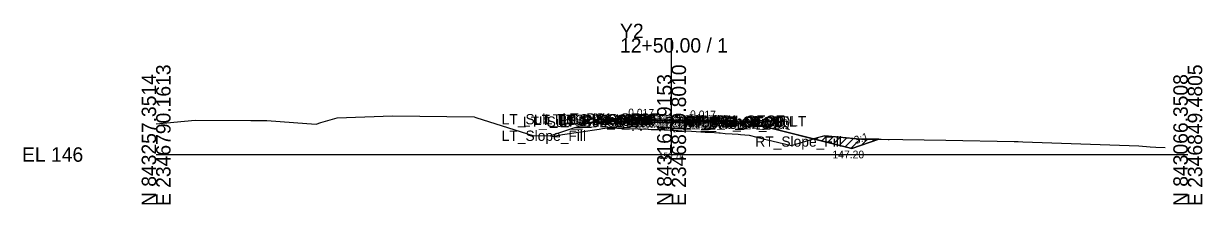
# Model space of a CAD drawing. Extents: x -26 to 2346977, y -10 to 843253.
# Drawn here: x -25.7 to 202.8, y 1990.3 to 2025.4 of the extents above; entities that cross this region are included whole.
import ezdxf

# ---------------------------------------------------------------- set-up
doc = ezdxf.new("R2010")
doc.units = 0
for name, color, linetype in [('Default', 7, 'Continuous'), ('Exist Cross Section Cell', 7, 'Continuous'), ('Exist XS Center Line Elevation Label', 7, 'Continuous'), ('Exist XS Ground Line', 7, 'Continuous'), ('Prop CMT Pvmt Course 1', 7, 'Continuous'), ('Prop CMT Pvmt Course 2', 7, 'Continuous'), ('Prop CMT Pvmt Course 3', 7, 'Continuous'), ('Prop CMT Pvmt Surface', 7, 'Continuous'), ('Prop CMT Pvmt Surface Shoulder', 7, 'Continuous'), ('Prop CMT Shld Paved Course 1', 7, 'Continuous'), ('Prop CMT Shld Paved Course 2', 7, 'Continuous'), ('Prop CMT Shld Paved Course 3', 7, 'Continuous'), ('Prop CMT Slope Grass', 7, 'Continuous'), ('Prop CMT Subgrade Earthwork', 7, 'Continuous'), ('Prop Road Sect_ Recs - UUC (Outline)', 7, 'Continuous'), ('Prop Road Sect_ Recs - UUC (pattern)', 7, 'Continuous'), ('Prop XS Earthwork Shape', 7, 'Continuous'), ('Prop XS SE Text', 7, 'Continuous'), ('Prop XS Side Slope Text', 7, 'Continuous'), ('Scratch_Level_2', 7, 'Continuous')]:
    doc.layers.add(name, color=color, linetype=linetype)

msp = doc.modelspace()

# ---------------------------------------------------------------- linework, layer by layer
at = {"layer": 'Exist Cross Section Cell'}
for p, q in [((99.93, 2000), (99.93, 2022.59)), ((0, 2000), (99.93, 2000)), ((99.93, 2000), (200, 2000))]:
    msp.add_line(p, q, dxfattribs=at)
at = {"layer": 'Exist XS Ground Line'}
msp.add_lwpolyline([(0, 2005.99), (7.59, 2006.64), (18.36, 2006.62), (21.44, 2006.61), (29.23, 2006.04), (31.01, 2005.92), (31.92, 2006.2), (35.07, 2007.11), (45.82, 2007.53), (61.63, 2007.29), (62.01, 2007.17), (73.2, 2003.61), (73.68, 2003.71), (76.58, 2003.65), (76.74, 2003.52), (78.79, 2003.86), (85.91, 2004.94), (86.54, 2005.04), (87.46, 2005.18), (88.16, 2005.17), (89.42, 2005.13), (90.77, 2005.08), (93.48, 2004.98), (95.41, 2004.91), (96, 2004.89), (97.41, 2004.83), (98.62, 2004.79), (100.02, 2004.73), (100.72, 2004.69), (101.19, 2004.66), (101.94, 2004.62), (103.82, 2004.52), (104.69, 2004.46), (106.44, 2004.36), (107.35, 2004.31), (109.08, 2004.2), (109.38, 2004.18), (110.35, 2004.11), (111.66, 2004.02), (112.82, 2003.93), (113.29, 2003.89), (114.97, 2003.73), (117.94, 2002.99), (118.53, 2002.84), (119.35, 2002.64), (123.16, 2001.78), (128.92, 2003.48), (129.66, 2003.65), (136.76, 2002.97), (140.55, 2002.96), (153.1, 2002.76), (166.33, 2002.54), (167.14, 2002.52), (168, 2002.46), (190.49, 2001.69), (192.73, 2001.49), (193.83, 2001.43), (195.59, 2001.34)], dxfattribs=at)
at = {"layer": 'Prop CMT Pvmt Course 1'}
for p, q in [((99.93, 2006.78), (88, 2006.99)), ((88, 2006.99), (88, 2006.74)), ((88, 2006.74), (99.93, 2006.53)), ((99.93, 2006.53), (99.93, 2006.78)), ((99.93, 2006.78), (112, 2006.58)), ((99.93, 2006.53), (99.93, 2006.78)), ((99.93, 2006.53), (99.93, 2006.66)), ((99.93, 2006.66), (99.93, 2006.66)), ((99.93, 2006.66), (99.93, 2006.53)), ((99.93, 2006.53), (99.93, 2006.66)), ((99.93, 2006.66), (99.93, 2006.66)), ((99.93, 2006.66), (99.93, 2006.53)), ((99.93, 2006.53), (99.93, 2006.53)), ((112, 2006.33), (99.93, 2006.53)), ((99.93, 2006.53), (99.93, 2006.53)), ((112, 2006.58), (112, 2006.33))]:
    msp.add_line(p, q, dxfattribs=at)
at = {"layer": 'Prop CMT Pvmt Course 2'}
for p, q in [((88, 2006.74), (99.93, 2006.53)), ((99.93, 2006.53), (88, 2006.74)), ((88, 2006.74), (88, 2006.74)), ((99.93, 2006.53), (99.93, 2006.53)), ((112, 2006.33), (99.93, 2006.53)), ((99.93, 2006.53), (99.93, 2006.53)), ((99.93, 2006.53), (112, 2006.33)), ((112, 2006.33), (112, 2006.33))]:
    msp.add_line(p, q, dxfattribs=at)
at = {"layer": 'Prop CMT Pvmt Course 3'}
for p, q in [((99.93, 2006.53), (88, 2006.74)), ((88, 2006.74), (88, 2006.4)), ((99.93, 2006.2), (99.93, 2006.53)), ((99.93, 2006.53), (112, 2006.33)), ((99.93, 2006.2), (99.93, 2006.53)), ((88, 2006.4), (99.93, 2006.2)), ((112, 2006), (99.93, 2006.2)), ((112, 2006.33), (112, 2006))]:
    msp.add_line(p, q, dxfattribs=at)
at = {"layer": 'Prop CMT Pvmt Surface'}
for q in [(88, 2006.99), (112, 2006.58)]:
    msp.add_line((99.93, 2006.78), q, dxfattribs=at)
at = {"layer": 'Prop CMT Pvmt Surface Shoulder'}
for p, q in [((88, 2006.99), (88, 2006.99)), ((112, 2006.58), (112, 2006.58))]:
    msp.add_line(p, q, dxfattribs=at)
at = {"layer": 'Prop CMT Shld Paved Course 1'}
for p, q in [((88, 2006.99), (87.74, 2006.73)), ((87.74, 2006.73), (88, 2006.74)), ((88, 2006.99), (88, 2006.99)), ((88, 2006.74), (88, 2006.99)), ((112, 2006.58), (112, 2006.58)), ((112, 2006.58), (112.25, 2006.32)), ((112, 2006.33), (112, 2006.58)), ((112.25, 2006.32), (112, 2006.33))]:
    msp.add_line(p, q, dxfattribs=at)
at = {"layer": 'Prop CMT Shld Paved Course 2'}
for p, q in [((88, 2006.74), (87.74, 2006.73)), ((87.74, 2006.73), (88, 2006.74)), ((87.74, 2006.73), (87.74, 2006.73)), ((88, 2006.74), (88, 2006.74)), ((112, 2006.33), (112.25, 2006.32)), ((112.25, 2006.32), (112, 2006.33)), ((112, 2006.33), (112, 2006.33)), ((112.25, 2006.32), (112.25, 2006.32))]:
    msp.add_line(p, q, dxfattribs=at)
at = {"layer": 'Prop CMT Shld Paved Course 3'}
for p, q in [((87.24, 2006.72), (86.9, 2006.38)), ((87.74, 2006.73), (87.24, 2006.72)), ((88, 2006.74), (87.74, 2006.73)), ((88, 2006.4), (88, 2006.74)), ((86.9, 2006.38), (88, 2006.4)), ((112, 2006.33), (112.25, 2006.32)), ((112, 2006), (112, 2006.33)), ((113.1, 2005.97), (112, 2006)), ((112.25, 2006.32), (112.75, 2006.31)), ((112.75, 2006.31), (113.1, 2005.97))]:
    msp.add_line(p, q, dxfattribs=at)
at = {"layer": 'Prop CMT Slope Grass'}
for p, q in [((86, 2006.83), (76.47, 2003.65)), ((88, 2006.99), (86, 2006.83)), ((112, 2006.58), (114, 2006.42)), ((114, 2006.42), (134.87, 2001.2)), ((134.87, 2001.2), (140.14, 2002.96))]:
    msp.add_line(p, q, dxfattribs=at)
at = {"layer": 'Prop CMT Subgrade Earthwork'}
for p, q in [((86.9, 2006.38), (86.43, 2006.86)), ((88, 2006.4), (86.9, 2006.38)), ((99.93, 2006.2), (88, 2006.4)), ((99.93, 2006.2), (112, 2006)), ((112, 2006), (113.1, 2005.97)), ((113.1, 2005.97), (113.57, 2006.45))]:
    msp.add_line(p, q, dxfattribs=at)
at = {"layer": 'Prop Road Sect_ Recs - UUC (Outline)'}
msp.add_lwpolyline([(127.47, 2003.05), (134.87, 2001.2), (134.87, 2001.2), (134.87, 2001.2), (140.13, 2002.95), (136.5, 2002.99), (129.66, 2003.65)], close=True, dxfattribs=at)
msp.add_lwpolyline([(127.47, 2003.05), (134.87, 2001.2), (134.87, 2001.2), (134.87, 2001.2), (140.13, 2002.95), (136.5, 2002.99), (129.66, 2003.65)], close=True, dxfattribs=at)
at = {"layer": 'Prop Road Sect_ Recs - UUC (pattern)'}
for p, q in [((127.95, 2002.93), (128.29, 2003.27)), ((127.95, 2002.93), (128.29, 2003.27)), ((129.08, 2002.65), (130.04, 2003.61)), ((129.08, 2002.65), (130.04, 2003.61)), ((130.21, 2002.37), (131.33, 2003.49)), ((130.21, 2002.37), (131.33, 2003.49)), ((131.34, 2002.08), (132.62, 2003.36)), ((131.34, 2002.08), (132.62, 2003.36)), ((132.47, 2001.8), (133.91, 2003.24)), ((132.47, 2001.8), (133.91, 2003.24)), ((133.61, 2001.52), (135.2, 2003.12)), ((133.61, 2001.52), (135.2, 2003.12)), ((134.74, 2001.23), (136.5, 2002.99)), ((134.74, 2001.23), (136.5, 2002.99)), ((136.77, 2001.84), (137.89, 2002.98)), ((136.77, 2001.84), (137.89, 2002.98)), ((138.86, 2002.53), (139.29, 2002.96)), ((138.86, 2002.53), (139.29, 2002.96)), ((141.97, 2002.81), (142.09, 2002.93)), ((141.97, 2002.81), (142.09, 2002.93))]:
    msp.add_line(p, q, dxfattribs=at)
at = {"layer": 'Prop XS Earthwork Shape'}
for points in [[(86.9, 2006.38), (86.43, 2006.86), (86, 2006.83), (76.47, 2003.65), (76.58, 2003.65), (76.74, 2003.52), (78.79, 2003.86), (85.91, 2004.94), (86.54, 2005.04), (87.46, 2005.18), (88.16, 2005.17), (89.42, 2005.13), (90.77, 2005.08), (93.48, 2004.98), (95.41, 2004.91), (96, 2004.89), (97.41, 2004.83), (98.62, 2004.79), (100.02, 2004.73), (100.72, 2004.69), (101.19, 2004.66), (101.94, 2004.62), (103.82, 2004.52), (104.69, 2004.46), (106.44, 2004.36), (107.35, 2004.31), (109.08, 2004.2), (109.38, 2004.18), (110.35, 2004.11), (111.66, 2004.02), (112.82, 2003.93), (113.29, 2003.89), (114.97, 2003.73), (117.94, 2002.99), (118.53, 2002.84), (119.35, 2002.64), (123.16, 2001.78), (127.47, 2003.05), (114, 2006.42), (113.57, 2006.45), (113.1, 2005.97), (112, 2006), (99.93, 2006.2), (88, 2006.4)], [(129.66, 2003.65), (136.76, 2002.97), (140.14, 2002.96), (134.87, 2001.2), (127.47, 2003.05), (128.92, 2003.48)]]:
    msp.add_lwpolyline(points, close=True, dxfattribs=at)

# ---------------------------------------------------------------- texts
at = {"layer": 'Default'}
for s, height, p in [('-', 0.0001, (0, 2000)), ('147.20', 1.5, (131.12, 1999.26))]:
    msp.add_text(s, height=height, dxfattribs=at).set_placement(p)
at = {"layer": 'Exist Cross Section Cell'}
for s, p in [('Y2', (89.93, 2022.59)), ('12+50.00 / 1', (89.93, 2019.79)), ('EL 146', (-26, 1998.6))]:
    msp.add_text(s, height=2.8, dxfattribs=at).set_placement(p)
for s, p in [('E 2346790.1613', (2.8, 1990)), ('E 2346819.8010', (102.73, 1990)), ('E 2346849.4805', (202.8, 1990)), ('N 843257.3514', (0, 1990)), ('N 843161.9153', (99.93, 1990)), ('N 843066.3508', (200, 1990))]:
    msp.add_text(s, height=2.8, rotation=90, dxfattribs=at).set_placement(p)
at = {"layer": 'Exist XS Center Line Elevation Label'}
msp.add_text('150.74', height=1.2, dxfattribs=at).set_placement((97.44, 1999.14))
at = {"layer": 'Prop XS SE Text'}
for s, rotation, p in [('0.017', 359.0299, (91.5, 2007.41)), ('0.017', 359.0299, (103.5, 2007.08)), ('4:1', 345.9638, (120.18, 2005.41)), ('3:1', 18.4349, (135.6, 2002.01))]:
    msp.add_text(s, height=1.5, rotation=rotation, dxfattribs=at).set_placement(p)
at = {"layer": 'Prop XS Side Slope Text'}
msp.add_text('3:1', height=1.5, rotation=18.4332, dxfattribs=at).set_placement((81.26, 2005.47))
at = {"layer": 'Scratch_Level_2'}
for s, p in [('LT_Sub_Trench_Out_DLT', (66.99, 2005.86)), ('LT_Sub_Trench_Out', (71.11, 2005.38)), ('LT_PS3_Shelf_Out', (73.23, 2005.72)), ('LT_GS_OS_CTL', (75.37, 2005.83)), ('LT_PS3_OEOP', (77.98, 2005.73)), ('LT_PS2_OEOP', (77.98, 2005.73)), ('LT_Sub_OEOT', (78.08, 2005.4)), ('LT_PV3_OEOT', (78.17, 2005.74)), ('LT_PV2_OEOT', (78.17, 2005.74)), ('LT_PV1_OEOT', (78.74, 2005.99)), ('LT_PS1_OEOP', (78.8, 2005.99)), ('RT_Sub_OEEOP', (89.1, 2005.2)), ('LT_Sub_OEEOP', (89.15, 2005.2)), ('RT_PV2_OEEOP', (89.19, 2005.53)), ('RT_PV3_OEEOP', (89.19, 2005.53)), ('LT_PV2_OEEOP', (89.24, 2005.53)), ('LT_PV3_OEEOP', (89.24, 2005.53)), ('RT_PV1_OEEOP', (89.76, 2005.66)), ('LT_PV1_OEEOP', (89.81, 2005.66)), ('RT_PV2_IEEOP', (89.84, 2005.53)), ('LT_PV2_IEEOP', (89.89, 2005.53)), ('RT_PV1_IEEOP', (90.41, 2005.66)), ('LT_PV1_IEEOP', (90.45, 2005.66)), ('PV2_PGL', (93.84, 2005.53)), ('RT_Sub_Trench_Out_DLT', (94.09, 2005.45)), ('PV1_PGL', (94.41, 2005.78)), ('RT_Sub_Trench_Out', (97.25, 2004.97)), ('RT_PS3_Shelf_Out', (98.69, 2005.31)), ('RT_Sub_OEOT', (102.03, 2005)), ('RT_PV3_OEOT', (102.13, 2005.33)), ('RT_PV2_OEOT', (102.13, 2005.33)), ('RT_PS3_OEOP', (102.44, 2005.32)), ('RT_PS2_OEOP', (102.44, 2005.32)), ('RT_PV1_OEOT', (102.69, 2005.58)), ('RT_PS1_OEOP', (102.76, 2005.58)), ('RT_GS_OS_CTL', (103.32, 2005.42)), ('LT_Slope_Fill', (66.99, 2002.65)), ('RT_Slope_Fill', (116.16, 2001.52))]:
    msp.add_text(s, height=2, dxfattribs=at).set_placement(p)

doc.saveas('drawing.dxf')
